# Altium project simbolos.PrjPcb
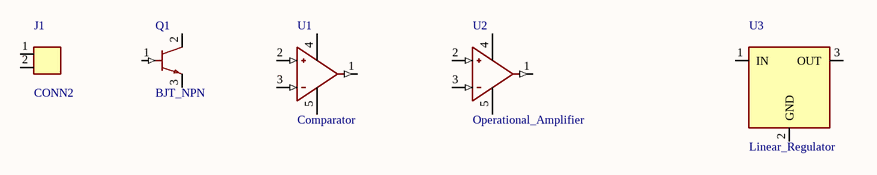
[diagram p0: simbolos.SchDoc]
1 sheet, 5 parts. Net scope: global (net labels, ports and power ports of the same name join across sheets).

## Sheet simbolos.SchDoc
size A4

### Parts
J1  CONN2
Q1  BJT_NPN
U1  Comparator
U2  Operational_Amplifier
U3  Linear_Regulator

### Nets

Not connected (* = marked no-connect by the designer): J1 1 2; Q1 1(B) 2(C) 3(E); U1 1 2(+) 3(-) 4(V+) 5(V-); U2 1 2(+) 3(-) 4(V+) 5(V-); U3 1(IN) 2(GND) 3(OUT)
